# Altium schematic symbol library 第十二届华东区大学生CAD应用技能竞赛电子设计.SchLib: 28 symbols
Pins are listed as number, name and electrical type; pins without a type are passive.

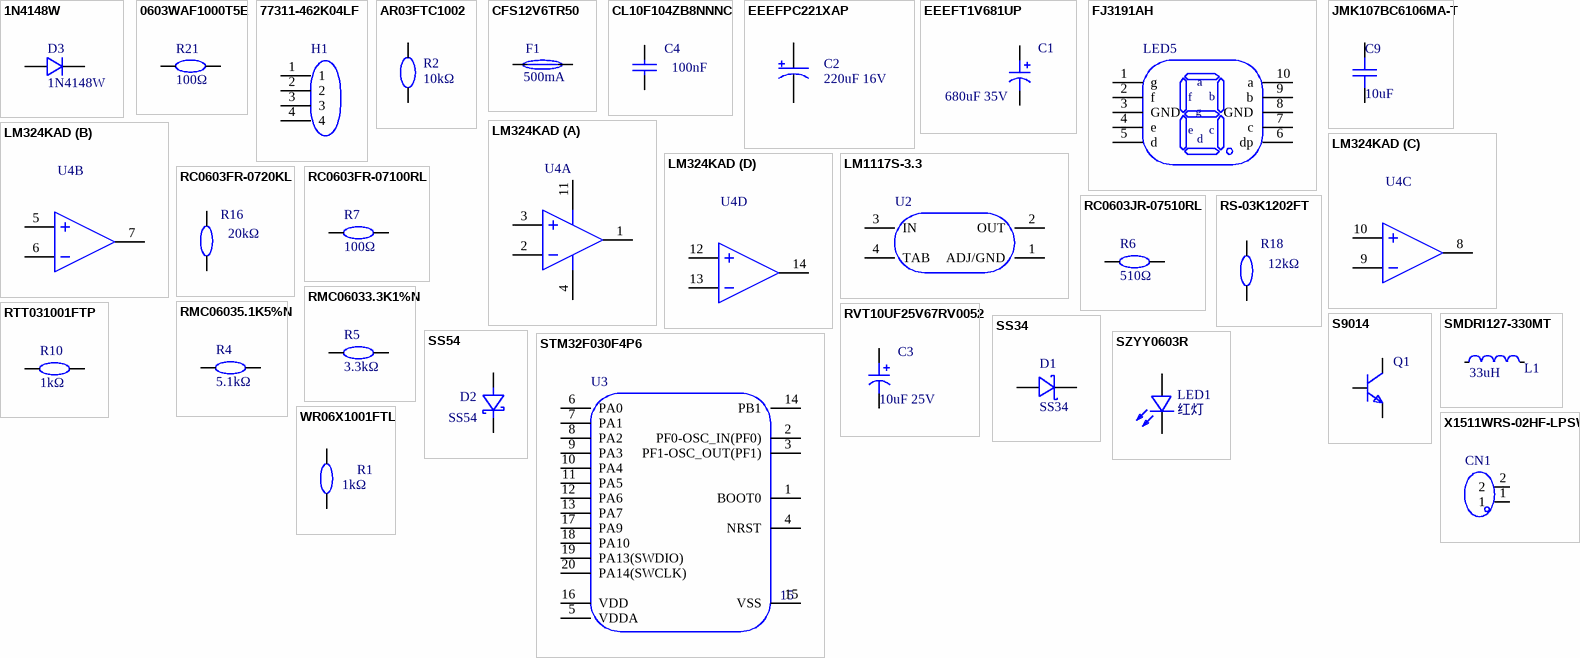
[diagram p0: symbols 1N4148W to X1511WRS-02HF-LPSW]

## 1N4148W
designator D3  Manufacturer Part: 1N4148W
Manufacturer: High Diode(海德); Symbol: 1N4148W_C466653; Add into BOM: yes; Diode Configuration: 独立式; Power Dissipation: 400mW; Reverse Voltage (Vr): 75V; Average Rectified Current (Io): 150mA; Forward Voltage (Vf@If): 1.25V@150mA; Reverse Leakage Current: 1A@75V; Reverse Recovery Time (trr): 4ns
footprint SOD-123_L2.7-W1.6-LS3.7-RD
pins: 1 K, 2 A

## 0603WAF1000T5E
designator R21  value 100Ω
Manufacturer: UNI-ROYAL(厚声); Symbol: 0603WAF1000T5E; Add into BOM: yes; Tolerance: ±1%; Power(Watts): 1/10W; Temperature Coefficient: ±200ppm/; Overload Voltage (Max): 75V
footprint R0603
pins: 1, 2

## 77311-462K04LF
designator H1
Manufacturer: Amphenol; Symbol: 77311-462K04LF; Add into BOM: yes; Pitch: 2.54mm
footprint HDR-TH_4P-P2.54-V-M-1
pins: 1, 2, 3, 4

## AR03FTC1002
designator R2  value 10kΩ
Manufacturer: 光颉(Viking); Symbol: AR03FTC1002; Add into BOM: yes; Tolerance: ±1%; Power(Watts): 62.5mW; Temperature Coefficient: ±25ppm/
footprint R0603
pins: 1, 2

## CFS12V6TR50
designator F1  Current Rating: 500mA
Manufacturer: 台湾大毅; Symbol: CFS12V6TR50; Add into BOM: yes; Fuse Type: 快速熔断; Rated Voltage(DC): 36V; Nominal Cold Resistance: 596mΩ; Breaking Capacity @ Rated Voltage: 50A; Melting I²t: 0.03
footprint F1206
pins: 1, 2

## CL10F104ZB8NNNC
designator C4  value 100nF
Manufacturer: SAMSUNG(三星); Symbol: CL10F104ZB8NNNC; Add into BOM: yes; Tolerance: -20%~+80%; Voltage Rated: 50V; Temperature Coefficient: Y5V
footprint C0603
pins: 1, 2

## EEEFPC221XAP
designator C2  LCSC Part Name: 220uF 16V
Manufacturer: PANASONIC(松下); Symbol: EEEFPC221XAP; Add into BOM: yes; Value: 220uF; Rated Voltage: 16V; φD: 6.3mm; L: 7.7mm; Lifetime @ Temp: 2000hrs@105
footprint CAP-SMD_BD6.3-L6.6-W6.6-FD
pins: 1, 2

## EEEFT1V681UP
designator C1  LCSC Part Name: 680uF 35V
Manufacturer: PANASONIC(松下); Symbol: EEEFT1V681UP; Add into BOM: yes; Value: 680uF; Rated Voltage: 35V
footprint CAP-SMD_BD10.0-L10.3-W10.3-FD
pins: 1, 2

## FJ3191AH
designator LED5
Manufacturer: 志浩; Symbol: FJ3191AH; Add into BOM: yes; Number of Characters: 1; Digit/Alpha Size: 0.39''(9.91mm); Common Pin: 阴极(负极); Illumination Color: 红色
footprint LED-SEG-TH_10P-L13.0-W10.0-P2.54-S7.62-BL
pins: 1 g, 2 f, 3 GND, 4 e, 5 d, 6 dp, 7 c, 8 GND, 9 b, 10 a

## JMK107BC6106MA-T
designator C9  value 10uF
Manufacturer: TAIYO YUDEN(太诱); Symbol: JMK107BC6106MA-T; Add into BOM: yes; Tolerance: ±20%
footprint C0603
pins: 1, 2

## LM324KAD
designator U4
Manufacturer: TI(德州仪器); Symbol: LM324KAD; Add into BOM: yes
footprint SOIC-14_L8.7-W3.9-P1.27-LS6.0-BL
part A pins: 1 OUT1, 2 IN1-, 3 IN1+, 4 VCC, 11 GND
part B pins: 5 IN2+, 6 IN2-, 7 OUT2
part C pins: 8 OUT3, 9 IN3-, 10 IN3+
part D pins: 12 IN4+, 13 IN4-, 14 OUT4

## LM1117S-3.3
designator U2
Manufacturer: HTC; Symbol: LM1117S-3.3; Add into BOM: yes; Output Type: 固定; Output Polarity: 正; Number of Outputs: 1; Maximum Input Voltage: 12V; Output Voltage: 3.3V; Dropout Voltage: 1.3V@(1A); Output Current: 1A; Power Supply Rejection Ratio (PRSS): 75dB@(120Hz)
footprint SOT-223-3_L6.5-W3.4-P2.30-LS7.0-BR
pins: 1 ADJ/GND, 2 OUT, 3 IN, 4 TAB

## RC0603FR-0720KL
designator R16  value 20kΩ
Manufacturer: YAGEO(国巨); Symbol: RC0603FR-0720KL; Add into BOM: yes; Tolerance: ±1%; Power(Watts): 100mW; Temperature Coefficient: ±100ppm/; Overload Voltage (Max): 75V
footprint R0603
pins: 1, 2

## RC0603FR-07100RL
designator R7  value 100Ω
Manufacturer: YAGEO(国巨); Symbol: RC0603FR-07100RL; Add into BOM: yes; Tolerance: ±1%; Power(Watts): 100mW; Temperature Coefficient: ±100ppm/; Overload Voltage (Max): 75V
footprint R0603
pins: 1, 2

## RC0603JR-07510RL
designator R6  value 510Ω
Manufacturer: YAGEO(国巨); Symbol: RC0603JR-07510RL; Add into BOM: yes; Tolerance: ±5%; Power(Watts): 100mW; Temperature Coefficient: ±100ppm/; Overload Voltage (Max): 75V
footprint R0603
pins: 1, 2

## RMC06033.3K1%N
designator R5  value 3.3kΩ
Manufacturer: Tyohm(幸亚电阻); Symbol: RMC06033.3K1%N; Add into BOM: yes; Tolerance: ±1%; Power(Watts): 0.1W
footprint R0603
pins: 1, 2

## RMC06035.1K5%N
designator R4  value 5.1kΩ
Manufacturer: Tyohm(幸亚电阻); Symbol: RMC06035.1K5%N; Add into BOM: yes; Tolerance: ±5%; Power(Watts): 0.1W
footprint R0603
pins: 1, 2

## RS-03K1202FT
designator R18  value 12kΩ
Manufacturer: FH(风华); Symbol: RS-03K1202FT; Add into BOM: yes; Tolerance: ±1%; Power(Watts): 100mW; Temperature Coefficient: ±100ppm/; Overload Voltage (Max): 50V
footprint R0603
pins: 1, 2

## RTT031001FTP
designator R10  value 1kΩ
Manufacturer: RALEC(旺诠); Symbol: RTT031001FTP; Add into BOM: yes; Tolerance: ±1%; Power(Watts): 0.1W; Temperature Coefficient: ±100ppm/
footprint R0603
3D model R0603_L1.6-W0.8-H0.8
pins: 1, 2

## RVT10UF25V67RV0052
designator C3  LCSC Part Name: 10uF 25V
Manufacturer: KNSCHA(科尼盛); Symbol: RVT10UF25V67RV0052; Add into BOM: yes; Lifetime @ Temp: 2000hrs@105
footprint CAP-SMD_BD4.0-L4.3-W4.3-LS5.0-FD
pins: 1, 2

## S9014
designator Q1
Manufacturer: TWGMC(台湾迪嘉); Symbol: S9014_C727140; Device: S9014; Add into BOM: yes; Transistor Type: NPN; Collector-Emitter Breakdown Voltage (Vceo): 45V; Collector Current (Ic): 100mA; Power Dissipation (Pd): 200mW; Collector-Emitter Saturation Voltage (VCE(sat)@Ic,Ib): 300mV@100mA,5mA; DC Current Gain (hFE@Ic,Vce): 200@1mA,5V; Transition Frequency (fT): 150MHz
footprint SOT-23-3_L2.9-W1.6-P1.90-LS2.8-BR
pins: 1 B, 2 E, 3 C

## SMDRI127-330MT
designator L1  value 33uH
Manufacturer: SXN(顺翔诺); Symbol: SMDRI127-330MT; Add into BOM: yes; Tolerance: ±20%; Rated Current: 3A; DC Resistance (DCR): 640mΩ
footprint IND-SMD_L12.3-W12.3
pins: 1, 2

## SS34
designator D1  LCSC Part Name: SS34
Manufacturer: MDD; Symbol: SS34_C8678; Add into BOM: yes
footprint DO-214AC_L4.3-W2.7-LS5.3-RD
pins: 1 K, 2 A

## SS54
designator D2  Device: SS54
Manufacturer: KUU; Symbol: SS54_C2891720; Add into BOM: yes; Reverse Voltage (Vr): 40V; Average Rectified Current (Io): 5A; Forward Voltage (Vf@If): 550mV@5A; Reverse Leakage Current (Ir): 500A@40V
footprint DO-214AC_L4.3-W2.7-LS5.3-RD
pins: 1 K, 2 A

## STM32F030F4P6
designator U3  NUMBER: 15
Manufacturer: ST(意法半导体); Symbol: STM32F030F4P6; Add into BOM: yes; Core Processor: ARM® Cortex®-M0; Voltage - Supply (Vcc/Vdd): 2.4V ~ 3.6V; Program Memory Size: 16KB; RAM Size: 4KB; A/D: 9X12bit; PWM: 6; UART/USART: 1 USART
footprint TSSOP-20_L6.5-W4.4-P0.65-LS6.4-BL
pins: 1 BOOT0, 2 PF0-OSC_IN(PF0), 3 PF1-OSC_OUT(PF1), 4 NRST, 5 VDDA, 6 PA0, 7 PA1, 8 PA2, 9 PA3, 10 PA4, 11 PA5, 12 PA6, 13 PA7, 14 PB1, 15 VSS, 16 VDD, 17 PA9, 18 PA10, 19 PA13(SWDIO), 20 PA14(SWCLK)

## SZYY0603R
designator LED1  Emitted Color: 红灯
Manufacturer: yongyu(永裕光电); Symbol: SZYY0603R; Add into BOM: yes; Lens Color: 无色透明; Dominant Wavelength: 615nm~630nm; Peak Wavelength: 645nm; Forward Current: 20mA; Forward Voltage (VF): 2.4V; Luminous Intensity: 300mcd; Power Dissipation: 40mW; Viewing Angle: 120°
footprint LED0603-R-RD
pins: 1 +, 2 -

## WR06X1001FTL
designator R1  value 1kΩ
Manufacturer: 华新科(Walsin); Symbol: WR06X1001FTL; Add into BOM: yes; Tolerance: ±1%; Power(Watts): 100mW; Temperature Coefficient: ±100ppm/; Overload Voltage (Max): 75V
footprint R0603
pins: 1, 2

## X1511WRS-02HF-LPSW
designator CN1
Manufacturer: XKB Connectivity(中国星坤); Symbol: X1511WRS-02HF-LPSW; Add into BOM: yes; Pitch: 1.5mm; Pins Structure: 1x2P; Number of PINs Per Row: 2; Gender: 公型插针; Current Rating (Max): 3A
footprint CONN-SMD_X1511WRS-02HF-LPSW
pins: 1, 2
